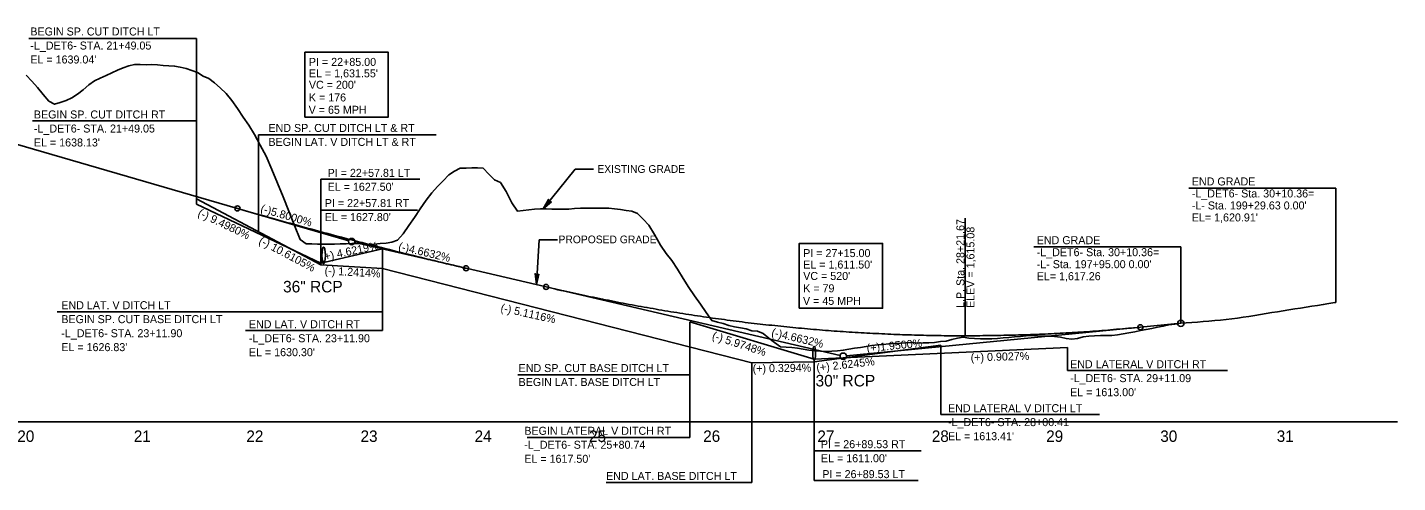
# Model space of a CAD drawing. Extents: x 498575 to 532350, y 405181 to 484585.
# Drawn here: x 514241 to 515440, y 436958 to 437357 of the extents above; entities that cross this region are included whole.
import ezdxf

# ---------------------------------------------------------------- set-up
doc = ezdxf.new("R2010")
doc.units = 0
for name, color, linetype in [('Exist Profile Cell', 7, 'Continuous'), ('Exist Vertical Profile Ground Line', 7, 'Continuous'), ('Exist Vertical Profile Horizontal Axis Label Major', 7, 'Continuous'), ('Prop Drainage Structure Pipe Welded Steel 54in Label', 7, 'Continuous'), ('Prop Grid Mask', 7, 'Continuous'), ('Prop PFL Text', 7, 'Continuous'), ('Prop Vertical Profile Curve Label', 7, 'Continuous'), ('Prop Vertical Profile Ditch Grade Left', 7, 'Continuous'), ('Prop Vertical Profile Ditch Grade Left Label', 7, 'Continuous'), ('Prop Vertical Profile Ditch Grade Right', 7, 'Continuous'), ('Prop Vertical Profile Ditch Grade Right Label', 7, 'Continuous'), ('Prop Vertical Profile Grade', 7, 'Continuous'), ('Prop Vertical Profile Grade Label', 7, 'Continuous'), ('Prop Vertical Profile Strip Grade', 7, 'Continuous'), ('Prop VPI Label', 7, 'Continuous'), ('Typical Terminator CELL', 7, 'Continuous')]:
    doc.layers.add(name, color=color, linetype=linetype)

# ---------------------------------------------------------------- blocks, each defined once
blk = doc.blocks.new('TERMINATOR')
at = {"layer": 'Typical Terminator CELL'}
blk.add_lwpolyline([(-0.469, 0.081), (0, 0), (-0.471, -0.083), (-0.411, 0)], close=True, dxfattribs=at)

msp = doc.modelspace()

# ---------------------------------------------------------------- linework, layer by layer
at = {"layer": 'Exist Profile Cell'}
msp.add_line((513239.8, 437011.5), (515439.8, 437011.5), dxfattribs=at)
at = {"layer": 'Exist Vertical Profile Ground Line'}
for points in [[(514239.8, 437315), (514244.8, 437309.7), (514249.8, 437304), (514254.8, 437298), (514259.8, 437292.1), (514264.8, 437289.4), (514269.8, 437290.9), (514274.8, 437292.6), (514279.8, 437295.2), (514284.8, 437298.3), (514289.8, 437302), (514294.8, 437306.5), (514299.8, 437310), (514304.8, 437312.3), (514309.8, 437314.6), (514314.8, 437316.9), (514319.8, 437319.4), (514324.8, 437321.4), (514329.8, 437323.2), (514334.8, 437324.1), (514339.8, 437324.3), (514344.8, 437323.9), (514349.8, 437324.2), (514354.8, 437323.8), (514359.8, 437323.4), (514364.8, 437323.2), (514369.8, 437322.8), (514374.8, 437321.8), (514379.8, 437320.7), (514384.8, 437319.1), (514389.8, 437317.3), (514394.8, 437314.1), (514399.8, 437312.1), (514404.8, 437308.1), (514409.8, 437303.9), (514414.8, 437298.8), (514419.8, 437292.8), (514424.8, 437285.7), (514429.8, 437278.2), (514434.8, 437271.1), (514439.8, 437263.1), (514444.8, 437253.6), (514449.8, 437243.9), (514454.8, 437232.4), (514459.8, 437220.5), (514464.8, 437208.5), (514469.8, 437196), (514474.8, 437183.4), (514479.8, 437171), (514484.8, 437167.2), (514489.8, 437167.2), (514494.8, 437167.1), (514499.8, 437167), (514504.8, 437166.9), (514509.8, 437167), (514514.8, 437167.2), (514519.8, 437167.4), (514524.8, 437167.6), (514529.8, 437167.7), (514534.8, 437167.3), (514539.8, 437166.8), (514544.8, 437167), (514549.8, 437167.6), (514554.8, 437168), (514559.8, 437168.7), (514564.8, 437170.5), (514569.8, 437176), (514574.8, 437183.3), (514579.8, 437190.4), (514584.8, 437197.9), (514589.8, 437205.5), (514594.8, 437211.8), (514599.8, 437217.5), (514604.8, 437222.4), (514609.8, 437227.6), (514614.8, 437231), (514619.8, 437233.4), (514624.8, 437233.4), (514629.8, 437233.7), (514634.8, 437233.7), (514639.8, 437233.4), (514644.8, 437228.2), (514649.8, 437223.2), (514654.8, 437221.1), (514659.8, 437213.2), (514664.8, 437203.2), (514669.8, 437195.9), (514674.8, 437196.4), (514679.8, 437197), (514684.8, 437197.5), (514689.8, 437197.8), (514694.8, 437197.8), (514699.8, 437197.7), (514704.8, 437197.7), (514709.8, 437197.7), (514714.8, 437197.7), (514719.8, 437198.1), (514724.8, 437198.5), (514729.8, 437198.5), (514734.8, 437198.5), (514739.8, 437198.5)], [(514739.8, 437198.5), (514744.8, 437198.4), (514749.8, 437198.4), (514754.8, 437197.9), (514759.8, 437197.3), (514764.8, 437196.6), (514769.8, 437195.9), (514774.8, 437193.9), (514779.8, 437188.8), (514784.8, 437183.6), (514789.8, 437175.6), (514794.8, 437166.2), (514799.8, 437158.9), (514804.8, 437152.6), (514809.8, 437145.1), (514814.8, 437137), (514819.8, 437129.2), (514824.8, 437121.7), (514829.8, 437114.5), (514834.8, 437107.1), (514839.8, 437100.1), (514844.8, 437098.8), (514849.8, 437097.5), (514854.8, 437095.9), (514859.8, 437094.8), (514864.8, 437093.9), (514869.8, 437092.9), (514874.8, 437091.3), (514879.8, 437090.9), (514884.8, 437088.9), (514889.8, 437084.9), (514894.8, 437080.9), (514899.8, 437077.1), (514904.8, 437076.8), (514909.8, 437076.5), (514914.8, 437075.9), (514919.8, 437075), (514924.8, 437074.2), (514929.8, 437073.7), (514934.8, 437073.3), (514939.8, 437073.1), (514944.8, 437073.3), (514949.8, 437073.8), (514954.8, 437074.2), (514959.8, 437075.1), (514964.8, 437076), (514969.8, 437076.7), (514974.8, 437077.5), (514979.8, 437078.2), (514984.8, 437078.8), (514989.8, 437079.3), (514994.8, 437079.8), (514999.8, 437080.2), (515004.8, 437080.5), (515009.8, 437080.8), (515014.8, 437080.9), (515019.8, 437080.5), (515024.8, 437080.6), (515029.8, 437080.8), (515034.8, 437081.1), (515039.8, 437081.9), (515044.8, 437082.1), (515049.8, 437083.5), (515054.8, 437084.7), (515059.8, 437085.5), (515064.8, 437084.9), (515069.8, 437084.6), (515074.8, 437084.3), (515079.8, 437084.2), (515084.8, 437084.3), (515089.8, 437084.4), (515094.8, 437085), (515099.8, 437085.4), (515104.8, 437085.8), (515109.8, 437086.3), (515114.8, 437086.8), (515119.8, 437087.2), (515124.8, 437086.9), (515129.8, 437086.5), (515134.8, 437086.4), (515139.8, 437086.3), (515144.8, 437085.5), (515149.8, 437084.6), (515154.8, 437083.8), (515159.8, 437084.6), (515164.8, 437085.9), (515169.8, 437086.5), (515174.8, 437086.9), (515179.8, 437087.2), (515184.8, 437087.2), (515189.8, 437087.2), (515194.8, 437087.8), (515199.8, 437088.6), (515204.8, 437089.5), (515209.8, 437090.4), (515214.8, 437091.4), (515219.8, 437092.4), (515224.8, 437093.3), (515229.8, 437094.3), (515234.8, 437095.2), (515239.8, 437096.3)], [(515239.8, 437096.3), (515244.8, 437097.1), (515249.8, 437097.8), (515254.8, 437098.2), (515259.8, 437098.5), (515264.8, 437098.9), (515269.8, 437099.2), (515274.8, 437099.7), (515279.8, 437100.1), (515284.8, 437100.6), (515289.8, 437101.2), (515294.8, 437101.8), (515299.8, 437102.4), (515304.8, 437103.1), (515309.8, 437103.8), (515314.8, 437104.6), (515319.8, 437105.4), (515324.8, 437106.3), (515329.8, 437107.1), (515334.8, 437107.9), (515339.8, 437108.7), (515344.8, 437109.5), (515349.8, 437110.3), (515354.8, 437111.1), (515359.8, 437111.9), (515364.8, 437112.7), (515369.8, 437113.4), (515374.8, 437114.2), (515379.8, 437115.1), (515384.8, 437115.9), (515385.9, 437116.1)]]:
    msp.add_lwpolyline(points, dxfattribs=at)
at = {"layer": 'Prop Drainage Structure Pipe Welded Steel 54in Label'}
for centre, major_axis in [((514500.2, 437157.2), (0, 7.5)), ((514929.4, 437071.5), (0, 6.25))]:
    msp.add_ellipse(centre, major_axis=major_axis, ratio=0.2, dxfattribs=at)
at = {"layer": 'Prop Grid Mask'}
for points in [[(514483.8, 437278.2), (514556.8, 437278.2), (514556.8, 437334.9), (514483.8, 437334.9)], [(514916.3, 437110.9), (514989.3, 437110.9), (514989.3, 437167.7), (514916.3, 437167.7)]]:
    msp.add_lwpolyline(points, close=True, dxfattribs=at)
at = {"layer": 'Prop PFL Text'}
for p, q in [((514720.3, 437232.7), (514692.3, 437197.8)), ((514736.3, 437232.7), (514720.3, 437232.7)), ((514688.8, 437170.9), (514686.3, 437131.6)), ((514704.8, 437170.9), (514688.8, 437170.9))]:
    msp.add_line(p, q, dxfattribs=at)
at = {"layer": 'Prop Vertical Profile Curve Label'}
for centre in [(514424.8, 437198.3), (514624.8, 437145.9), (514694.8, 437129.6), (515214.8, 437094.3)]:
    msp.add_circle(centre, 2.25, dxfattribs=at)
at = {"layer": 'Prop Vertical Profile Ditch Grade Left'}
for points in [[(514388.9, 437206.7), (514388.9, 437206.7), (514497.7, 437149), (514551.7, 437145.6)], [(514551.7, 437145.6), (514551.7, 437145.6), (514874.7, 437063.1), (514874.7, 437063.1), (514929.4, 437064), (515040.3, 437078.5)]]:
    msp.add_lwpolyline(points, dxfattribs=at)
at = {"layer": 'Prop Vertical Profile Ditch Grade Left Label'}
for p, q in [((514242.2, 437346.9), (514388.9, 437346.9)), ((514388.9, 437206.7), (514388.9, 437346.9)), ((514443.2, 437262.7), (514598.6, 437262.7)), ((514443.2, 437177.9), (514443.2, 437262.7)), ((514497.7, 437223.8), (514584.4, 437223.8)), ((514497.7, 437149), (514497.7, 437223.8)), ((514551.7, 437145.6), (514551.7, 437107.7)), ((514267, 437107.7), (514551.7, 437107.7)), ((514820.6, 437076.9), (514820.6, 437052.6)), ((515040.3, 437078.5), (515040.3, 437018)), ((514874.7, 437063.1), (514874.7, 436958.4)), ((514929.4, 437064), (514929.4, 436960.3)), ((514670.1, 437052.6), (514820.6, 437052.6)), ((515040.3, 437018), (515178.9, 437018)), ((514747.3, 436958.4), (514874.7, 436958.4)), ((514929.4, 436960.3), (515020.4, 436960.3))]:
    msp.add_line(p, q, dxfattribs=at)
at = {"layer": 'Prop Vertical Profile Ditch Grade Right'}
for points in [[(514388.9, 437202.1), (514497.7, 437150.5), (514551.7, 437163), (514551.7, 437163), (514551.7, 437163)], [(514820.6, 437099), (514929.4, 437066.5), (515150.9, 437076.5), (515150.9, 437076.5), (515150.9, 437076.5)]]:
    msp.add_lwpolyline(points, dxfattribs=at)
at = {"layer": 'Prop Vertical Profile Ditch Grade Right Label'}
for p, q in [((514388.9, 437275), (514245.5, 437275)), ((514388.9, 437275), (514388.9, 437202.1)), ((514497.7, 437196.8), (514497.7, 437150.5)), ((514582.4, 437196.8), (514497.7, 437196.8)), ((514551.7, 437091.5), (514551.7, 437163)), ((514820.6, 436997.9), (514820.6, 437099)), ((514551.7, 437091.5), (514431.7, 437091.5)), ((515150.9, 437056.5), (515150.9, 437076.5)), ((514929.4, 436986.3), (514929.4, 437066.5)), ((515291.1, 437056.5), (515150.9, 437056.5)), ((514820.6, 436997.9), (514678.3, 436997.9)), ((515023.1, 436986.3), (514929.4, 436986.3))]:
    msp.add_line(p, q, dxfattribs=at)
at = {"layer": 'Prop Vertical Profile Grade'}
for p, q in [((514109.8, 437289.6), (514424.8, 437198.3)), ((514624.8, 437145.9), (514694.8, 437129.6)), ((515214.8, 437094.3), (515250.2, 437097.8))]:
    msp.add_line(p, q, dxfattribs=at)
for points in [[(514424.8, 437198.3), (514428.8, 437197.1), (514432.8, 437195.9), (514436.8, 437194.8), (514440.8, 437193.7), (514444.8, 437192.5), (514448.8, 437191.4), (514452.8, 437190.2), (514456.8, 437189.1), (514460.8, 437188), (514464.8, 437186.9), (514468.8, 437185.8), (514472.8, 437184.7), (514476.8, 437183.6), (514480.8, 437182.5), (514484.8, 437181.4), (514488.8, 437180.3), (514492.8, 437179.2), (514496.8, 437178.1), (514500.8, 437177), (514504.8, 437176), (514508.8, 437174.9), (514512.8, 437173.8), (514516.8, 437172.8), (514520.8, 437171.7), (514524.8, 437170.7), (514528.8, 437169.6), (514532.8, 437168.6), (514536.8, 437167.6), (514540.8, 437166.5), (514544.8, 437165.5), (514548.8, 437164.5), (514552.8, 437163.5), (514556.8, 437162.5), (514560.8, 437161.4), (514564.8, 437160.4), (514568.8, 437159.4), (514572.8, 437158.4), (514576.8, 437157.5), (514580.8, 437156.5), (514584.8, 437155.5), (514588.8, 437154.5), (514592.8, 437153.5), (514596.8, 437152.6), (514600.8, 437151.6), (514604.8, 437150.7), (514608.8, 437149.7), (514612.8, 437148.8), (514616.8, 437147.8), (514620.8, 437146.9), (514624.8, 437145.9)], [(514694.8, 437129.6), (514705.2, 437127.2), (514715.6, 437124.9), (514726, 437122.7), (514736.4, 437120.5), (514746.8, 437118.4), (514757.2, 437116.3), (514767.6, 437114.3), (514778, 437112.4), (514788.4, 437110.6), (514798.8, 437108.8), (514809.2, 437107.1), (514819.6, 437105.5), (514830, 437103.9), (514840.4, 437102.4), (514850.8, 437101), (514861.2, 437099.6), (514871.6, 437098.3), (514882, 437097.1), (514892.4, 437096), (514902.8, 437094.9), (514913.2, 437093.9), (514923.6, 437092.9), (514934, 437092), (514944.4, 437091.2), (514954.8, 437090.5), (514965.2, 437089.8), (514975.6, 437089.2), (514986, 437088.7), (514996.4, 437088.2), (515006.8, 437087.8), (515017.2, 437087.5), (515027.6, 437087.2), (515038, 437087), (515048.4, 437086.9), (515058.8, 437086.9), (515069.2, 437086.9), (515079.6, 437087), (515090, 437087.1), (515100.4, 437087.4), (515110.8, 437087.6), (515121.2, 437088), (515131.6, 437088.4), (515142, 437088.9), (515152.4, 437089.5), (515162.8, 437090.1), (515173.2, 437090.8), (515183.6, 437091.6), (515194, 437092.5), (515204.4, 437093.4), (515214.8, 437094.3)]]:
    msp.add_spline(points, degree=3, dxfattribs=at)
at = {"layer": 'Prop Vertical Profile Strip Grade'}
msp.add_line((515061.5, 437189.7), (515061.5, 437086.9), dxfattribs=at)
at = {"layer": 'Prop VPI Label'}
for p, q in [((515385.9, 437216.1), (515257.3, 437216.1)), ((515385.9, 437116.1), (515385.9, 437216.1)), ((514424.8, 437198.3), (514522.2, 437170)), ((514624.8, 437145.9), (514527.5, 437168.6)), ((515250.2, 437164.7), (515121.7, 437164.7)), ((515250.2, 437097.8), (515250.2, 437164.7)), ((514694.8, 437129.6), (514952.2, 437069.6)), ((515214.8, 437094.3), (514957.6, 437069.3))]:
    msp.add_line(p, q, dxfattribs=at)
for centre in [(514524.8, 437169.3), (515250.2, 437097.8), (514954.8, 437069)]:
    msp.add_circle(centre, 2.75, dxfattribs=at)

# ---------------------------------------------------------------- block references
at = {"layer": 'Prop PFL Text', "xscale": 20}
for p, yscale, rotation in [((514692.3, 437197.8), 20, -128.69507200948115), ((514686.3, 437131.6), 19.999999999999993, -93.70508386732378)]:
    msp.add_blockref('TERMINATOR', p, dxfattribs=dict(at, yscale=yscale, rotation=rotation))

# ---------------------------------------------------------------- texts
at = {"layer": 'Exist Vertical Profile Horizontal Axis Label Major'}
for s, p in [('20', (514232.2, 436994)), ('21', (514334.1, 436994)), ('22', (514432.6, 436994)), ('23', (514532.5, 436994)), ('24', (514632.3, 436994)), ('25', (514732.4, 436994)), ('26', (514832.3, 436994)), ('27', (514932.2, 436994)), ('28', (515032.3, 436994)), ('29', (515132.4, 436994)), ('30', (515232.2, 436994)), ('31', (515334.1, 436994))]:
    msp.add_text(s, height=10, dxfattribs=at).set_placement(p)
at = {"layer": 'Prop Drainage Structure Pipe Welded Steel 54in Label'}
for s, p in [('36" RCP', (514464.7, 437124.8)), ('30" RCP', (514930.6, 437042.5))]:
    msp.add_text(s, height=10.12, dxfattribs=at).set_placement(p)
at = {"layer": 'Prop PFL Text'}
for s, p in [('EXISTING GRADE', (514739.7, 437229.4)), ('PROPOSED GRADE', (514705.7, 437167.8))]:
    msp.add_text(s, height=6.75, dxfattribs=at).set_placement(p)
at = {"layer": 'Prop Vertical Profile Curve Label'}
for s, p in [("VC = 200'", (514487.3, 437303)), ('K = 176', (514487.3, 437291.9)), ('V = 65 MPH ', (514487.1, 437281.1)), ("VC = 520'", (514919.8, 437135.7)), ('K = 79', (514919.8, 437124.9)), ('V = 45 MPH ', (514919.6, 437113.9))]:
    msp.add_text(s, height=7, dxfattribs=at).set_placement(p)
at = {"layer": 'Prop Vertical Profile Ditch Grade Left Label'}
for s, rotation, p in [('BEGIN SP. CUT DITCH LT', 360, (514243.6, 437349.6)), ('-L_DET6- STA. 21+49.05', 360, (514243.6, 437337.3)), ("EL = 1639.04'", 360, (514243.6, 437325.1)), ('END SP. CUT DITCH LT & RT', 360, (514451.9, 437265.2)), ('BEGIN LAT. V DITCH LT & RT', 360, (514451.9, 437253)), ('PI = 22+57.81 LT', 360, (514503.7, 437225.9)), ("EL = 1627.50'", 360, (514503.7, 437213.7)), ('(-) 10.6105%', 332.0437, (514442.8, 437167.9)), ('(-) 1.2414%', 356.8313, (514500.9, 437140.5)), ('END LAT. V DITCH LT', 360, (514270.7, 437110.1)), ('BEGIN SP. CUT BASE DITCH LT', 360, (514270.7, 437097.9)), ('(-) 5.1116%', 347.4975, (514654.6, 437108.2)), ('-L_DET6- STA. 23+11.90', 360, (514270.7, 437085.6)), ("EL = 1626.83'", 360, (514270.7, 437073.4)), ('END SP. CUT BASE DITCH LT', 360, (514670.8, 437055.1)), ('(+) 0.3294%', 0.7584, (514875.6, 437054.8)), ('(+) 2.6245%', 6.3671, (514931.7, 437055.4)), ('BEGIN LAT. BASE DITCH LT', 360, (514670.8, 437042.9)), ('END LATERAL V DITCH LT', 360, (515046.5, 437020)), ('-L_DET6- STA. 28+00.41', 360, (515046.5, 437007.8)), ("EL = 1613.41'", 360, (515046.5, 436995.5)), ('END LAT. BASE DITCH LT', 360, (514747.3, 436960.7)), ('PI = 26+89.53 LT', 360, (514936.5, 436962.3))]:
    msp.add_text(s, height=7, rotation=rotation, dxfattribs=at).set_placement(p)
at = {"layer": 'Prop Vertical Profile Ditch Grade Right Label'}
for s, rotation, p in [('BEGIN SP. CUT DITCH RT', 360, (514246.7, 437277)), ('-L_DET6- STA. 21+49.05', 360, (514246.7, 437264.7)), ("EL = 1638.13'", 360, (514246.7, 437252.5)), ('PI = 22+57.81 RT', 360, (514501.2, 437199.5)), ('(-) 9.4980%', 334.5437, (514389.5, 437192)), ("EL = 1627.80'", 360, (514501.2, 437187.2)), ('(+) 4.6219%', 11.991, (514498.5, 437152)), ('END LAT. V DITCH RT', 360, (514434.8, 437093.5)), ('-L_DET6- STA. 23+11.90', 360, (514434.8, 437081.2)), ('(-) 5.9748%', 341.9069, (514839.5, 437084.1)), ("EL = 1630.30'", 360, (514434.8, 437069)), ('(+) 0.9027%', 1.5507, (515066.4, 437064.4)), ('END LATERAL V DITCH RT', 360, (515153.3, 437058.5)), ('-L_DET6- STA. 29+11.09', 360, (515153.3, 437046.3)), ("EL = 1613.00'", 360, (515153.3, 437034)), ('BEGIN LATERAL V DITCH RT', 360, (514675.8, 437000.2)), ('-L_DET6- STA. 25+80.74', 360, (514675.8, 436988)), ('PI = 26+89.53 RT', 360, (514935.3, 436988.5)), ("EL = 1617.50'", 360, (514675.8, 436975.7)), ("EL = 1611.00'", 360, (514935.3, 436976.2))]:
    msp.add_text(s, height=7, rotation=rotation, dxfattribs=at).set_placement(p)
at = {"layer": 'Prop Vertical Profile Grade Label'}
for s, rotation, p in [('(-)5.8000%', 343.8278, (514444.4, 437195.2)), ('(-)4.6632%', 346.8755, (514565.1, 437161.9)), ('(-)4.6632%', 346.8755, (514891.5, 437086.7)), ('(+)1.9500%', 5.5687, (514975.7, 437072.5))]:
    msp.add_text(s, height=7, rotation=rotation, dxfattribs=at).set_placement(p)
at = {"layer": 'Prop Vertical Profile Strip Grade'}
for s, p in [('L.P. Sta. 28+21.67', (515060.8, 437111.2)), ('ELEV = 1,615.08', (515069.6, 437111.2))]:
    msp.add_text(s, height=7, rotation=90, dxfattribs=at).set_placement(p)
at = {"layer": 'Prop VPI Label'}
for s, p in [('PI = 22+85.00', (514487.3, 437323)), ("EL = 1,631.55'", (514487.3, 437313)), ('END GRADE', (515259.8, 437218.4)), ('-L_DET6- Sta. 30+10.36=', (515259.8, 437207.9)), ("-L- Sta. 199+29.63 0.00' ", (515259.8, 437197.4)), ("EL= 1,620.91'", (515259.8, 437186.9)), ('END GRADE', (515124.1, 437167)), ('PI = 27+15.00', (514919.8, 437155.7)), ("EL = 1,611.50'", (514919.8, 437145.7)), ('-L_DET6- Sta. 30+10.36=', (515124.1, 437156.5)), ("-L- Sta. 197+95.00 0.00' ", (515124.1, 437146)), ('EL= 1,617.26', (515124.1, 437135.5))]:
    msp.add_text(s, height=7, dxfattribs=at).set_placement(p)

doc.saveas('drawing.dxf')
